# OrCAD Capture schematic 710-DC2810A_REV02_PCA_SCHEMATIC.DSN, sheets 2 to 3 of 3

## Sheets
2 LTM4673_PAGE2: size Custom
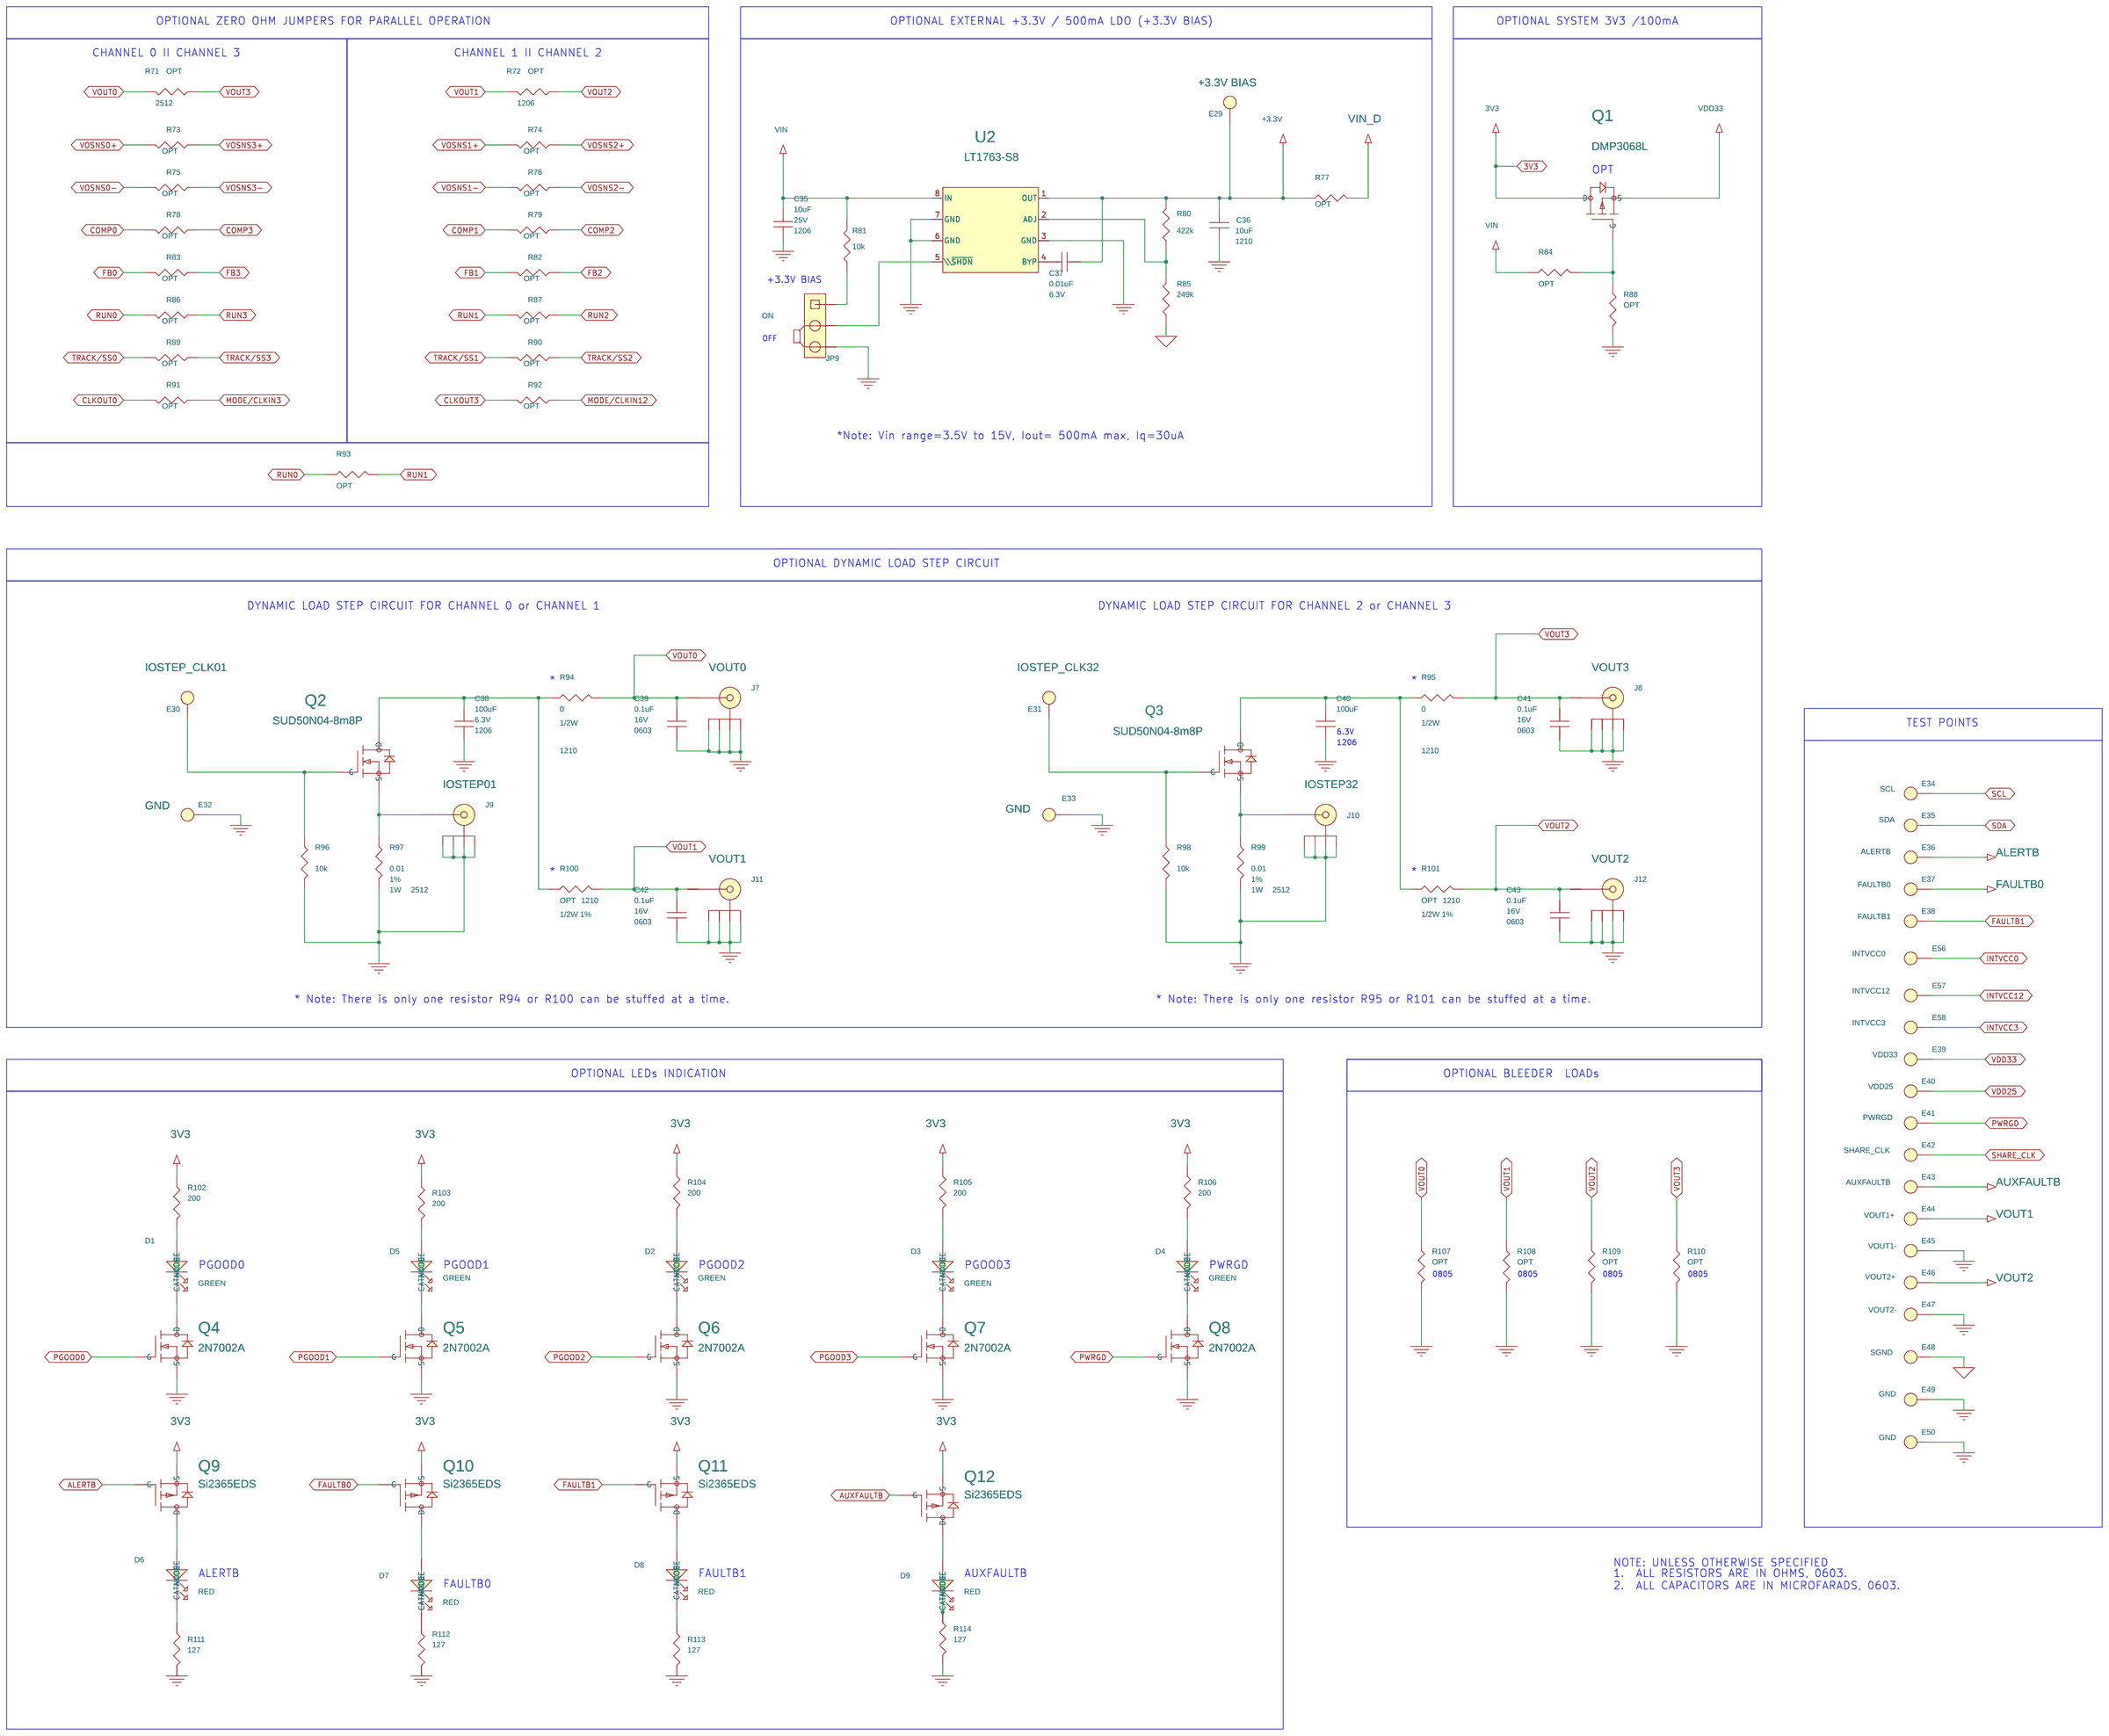
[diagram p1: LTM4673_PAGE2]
3 LTM4673_PAGE3: size Custom
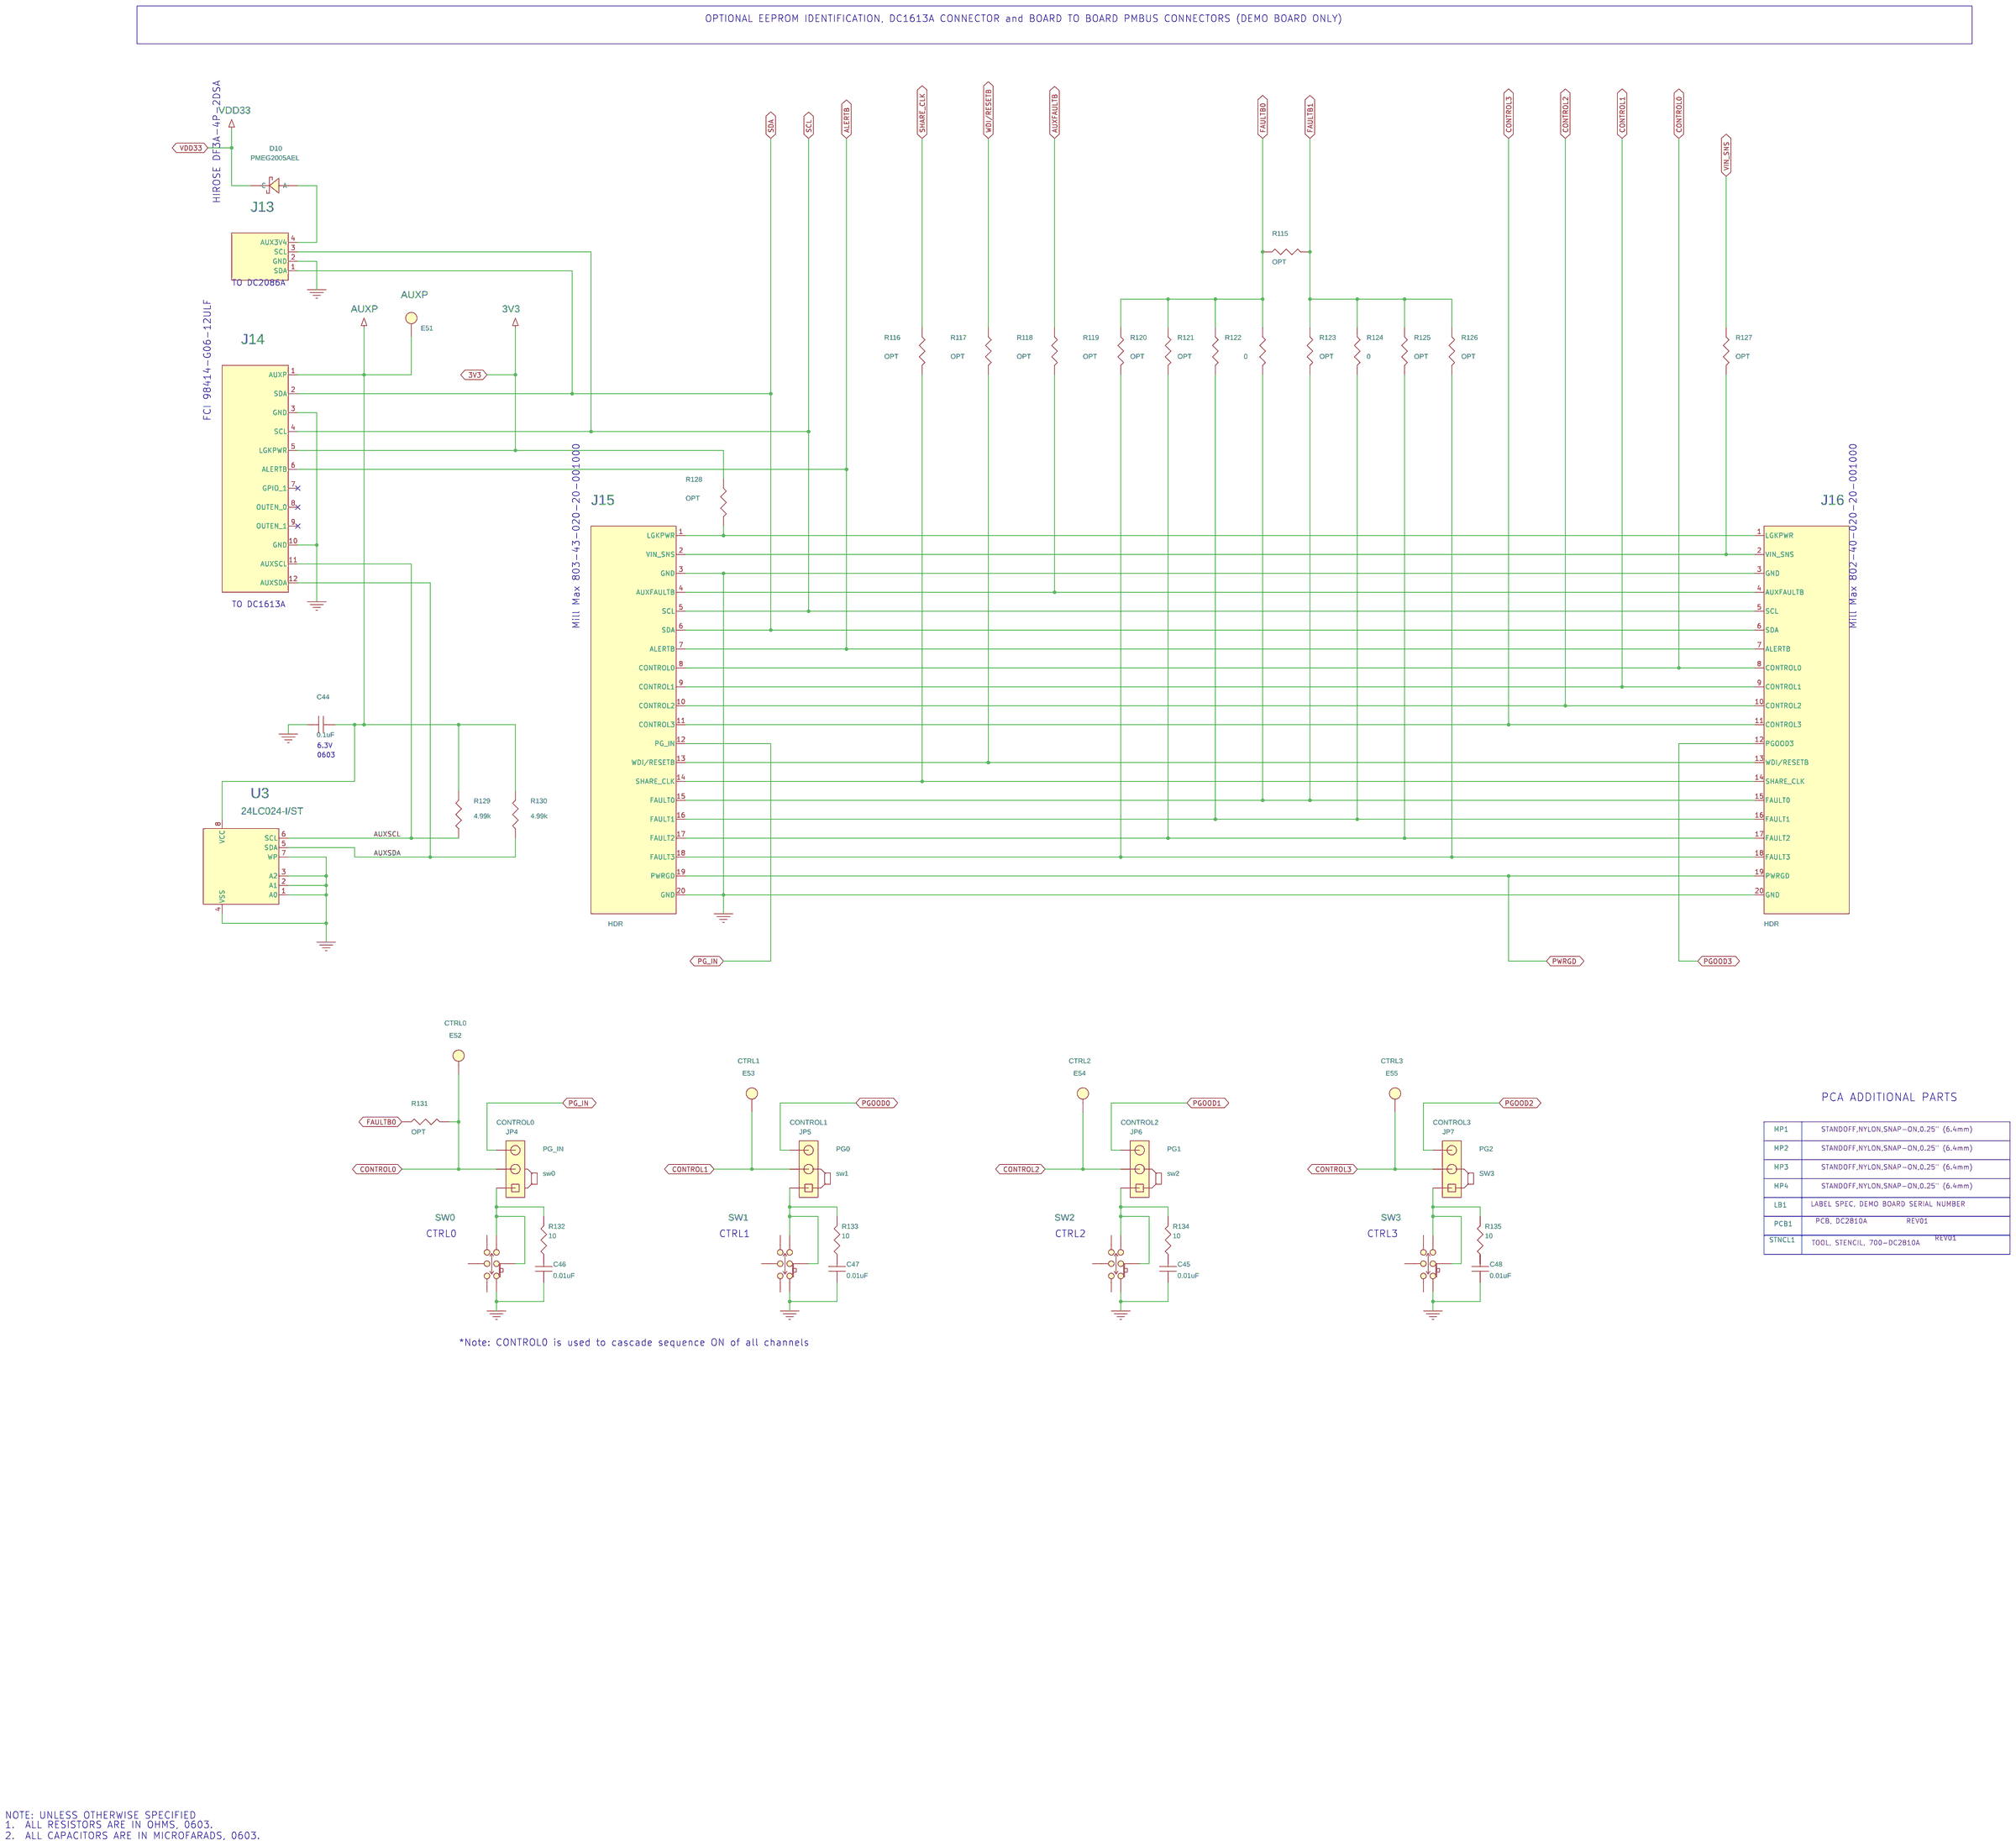
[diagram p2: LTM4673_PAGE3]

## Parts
sheet LTM4673_PAGE2
C35  10uF  [CC1206N]
C36  10uF  [CC1210N]
C37  0.01uF  [CC0603N]
C38  100uF  [CC1206N]
C39  0.1uF  [CC0603N]
C40  100uF  [CC1206N]
C41  0.1uF  [CC0603N]
C42  0.1uF  [CC0603N]
C43  0.1uF  [CC0603N]
D1  GREEN  [LED_0603]
D2  GREEN  [LED_0603]
D3  GREEN  [LED_0603]
D4  GREEN  [LED_0603]
D5  GREEN  [LED_0603]
D6  RED  [LED_0603]
D7  RED  [LED_0603]
D8  RED  [LED_0603]
D9  RED  [LED_0603]
E29  TEST POINT  [MILLMAX2308]
E30  TEST POINT  [MILLMAX2308]
E31  TEST POINT  [MILLMAX2308]
E32  TEST POINT  [MILLMAX2308]
E33  TEST POINT  [MILLMAX2308]
E34  TEST POINT  [MILLMAX2308]
E35  TEST POINT  [MILLMAX2308]
E36  TEST POINT  [MILLMAX2308]
E37  TEST POINT  [MILLMAX2308]
E38  TEST POINT  [MILLMAX2308]
E39  TEST POINT  [MILLMAX2308]
E40  TEST POINT  [MILLMAX2308]
E41  TEST POINT  [MILLMAX2308]
E42  TEST POINT  [MILLMAX2308]
E43  TEST POINT  [MILLMAX2308]
E44  TEST POINT  [MILLMAX2308]
E45  TEST POINT  [MILLMAX2308]
E46  TEST POINT  [MILLMAX2308]
E47  TEST POINT  [MILLMAX2308]
E48  TEST POINT  [MILLMAX2308]
E49  TEST POINT  [MILLMAX2308]
E50  TEST POINT  [MILLMAX2308]
E56  TEST POINT  [MILLMAX2308]
E57  TEST POINT  [MILLMAX2308]
E58  TEST POINT  [MILLMAX2308]
J7  RF,BNC  [CONNEX-112404]
J8  RF,BNC  [CONNEX-112404]
J9  RF,BNC  [CONNEX-112404]
J10  RF,BNC  [CONNEX-112404]
J11  RF,BNC  [CONNEX-112404]
J12  RF,BNC  [CONNEX-112404]
JP9  HDR.  [HD1X3-079]
Q1  DMP3068L  [SOT23-3N]
Q2  SUD50N04-8m8P  [TO-252-3N]
Q3  SUD50N04-8m8P  [TO-252-3N]
Q4  2N7002A  [SOT23-3N]
Q5  2N7002A  [SOT23-3N]
Q6  2N7002A  [SOT23-3N]
Q7  2N7002A  [SOT23-3N]
Q8  2N7002A  [SOT23-3N]
Q9  Si2365EDS  [SOT23-3N]
Q10  Si2365EDS  [SOT23-3N]
Q11  Si2365EDS  [SOT23-3N]
Q12  Si2365EDS  [SOT23-3N]
R71  OPT  [CR2512N]
R72  OPT  [CR1206N]
R73  OPT  [CR0603N]
R74  OPT  [CR0603N]
R75  OPT  [CR0603N]
R76  OPT  [CR0603N]
R77  OPT  [CR0603N]
R78  OPT  [CR0603N]
R79  OPT  [CR0603N]
R80  422k  [CR0603N]
R81  10k  [CR0603N]
R82  OPT  [CR0603N]
R83  OPT  [CR0603N]
R84  OPT  [CR0603N]
R85  249k  [CR0603N]
R86  OPT  [CR0603N]
R87  OPT  [CR0603N]
R88  OPT  [CR0603N]
R89  OPT  [CR0603N]
R90  OPT  [CR0603N]
R91  OPT  [CR0603N]
R92  OPT  [CR0603N]
R93  OPT  [CR0603N]
R94  0  [CR1210N]
R95  0  [CR1210N]
R96  10k  [CR0603N]
R97  0.01  [PANASONIC-ERJM1WS]
R98  10k  [CR0603N]
R99  0.01  [PANASONIC-ERJM1WS]
R100  OPT  [CR1210N]
R101  OPT  [CR1210N]
R102  200  [CR0603N]
R103  200  [CR0603N]
R104  200  [CR0603N]
R105  200  [CR0603N]
R106  200  [CR0603N]
R107  OPT  [CR0603N]
R108  OPT  [CR0603N]
R109  OPT  [CR0603N]
R110  OPT  [CR0603N]
R111  127  [CR0603N]
R112  127  [CR0603N]
R113  127  [CR0603N]
R114  127  [CR0603N]
U2  LT1763-S8  [LTC-S8-8-1610(S8)]
XJP9  SHUNT
sheet LTM4673_PAGE3
C44  0.1uF  [CC0603N]
C45  0.01uF  [CC0603N]
C46  0.01uF  [CC0603N]
C47  0.01uF  [CC0603N]
C48  0.01uF  [CC0603N]
D10  PMEG2005AEL  [SOD-882N]
E51  TEST POINT  [MILLMAX2308]
E52  TEST POINT  [MILLMAX2308]
E53  TEST POINT  [MILLMAX2308]
E54  TEST POINT  [MILLMAX2308]
E55  TEST POINT  [MILLMAX2308]
J13  SHROUDED HDR  [HIROSE-DF3A-4P-2DSA]
J14  SHROUDED HDR  [HD2X6-079-MOLEX]
J15  HDR  [MILL-MAX-803-43-020-20-001000]
J16  HDR  [MILL-MAX-802-40-020-20-001000]
JP4  HDR.  [HD1X3-079]
JP5  HDR.  [HD1X3-079]
JP6  HDR.  [HD1X3-079]
JP7  HDR.  [HD1X3-079]
LB1  LABEL  [895-0154_REV01]
MP1  STANDOFF  [MTG-8831]
MP2  STANDOFF  [MTG-8831]
MP3  STANDOFF  [MTG-8831]
MP4  STANDOFF  [MTG-8831]
PCB1  PCB, DC2810A
R115  OPT  [CR0603N]
R116  OPT  [CR0603N]
R117  OPT  [CR0603N]
R118  OPT  [CR0603N]
R119  OPT  [CR0603N]
R120  OPT  [CR0603N]
R121  OPT  [CR0603N]
R122  0  [CR0603N]
R123  OPT  [CR0603N]
R124  0  [CR0603N]
R125  OPT  [CR0603N]
R126  OPT  [CR0603N]
R127  OPT  [CR0603N]
R128  OPT  [CR0603N]
R129  4.99k  [CR0603N]
R130  4.99k  [CR0603N]
R131  OPT  [CR0603N]
R132  10  [CR0603N]
R133  10  [CR0603N]
R134  10  [CR0603N]
R135  10  [CR0603N]
STNCL1  TOOL, STENCIL, 700-DC2810A
SW0  DPDT  [CK-JS202011CQN]
SW1  DPDT  [CK-JS202011CQN]
SW2  DPDT  [CK-JS202011CQN]
SW3  DPDT  [CK-JS202011CQN]
U3  24LC024-I/ST  [MICROCHIP-TSSOP-8]
XJP4  SHUNT
XJP5  SHUNT
XJP6  SHUNT
XJP7  SHUNT

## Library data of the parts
C35 = CAP: CAP.,10uF,X7R,25V,10%,1206; CLASS: DISCRETE; Dielectric Type: X7R; FPLIST: CC1206N,CC1206L,CC1206M; Inventory Qty: 16158; Manufacturer: AVX; Manufacturer PN: 12063C106KAT2A; PART_NUMBER: 150-3318; Package Size: 1206; Rated Voltage: 25V; Tolerance: 10%
C36 = CAP: CAP.,10uF,X5R,16V,20%,1210; ALT_SYMBOLS: CC1210M, CC1210L; CLASS: DISCRETE; Dielectric Type: X5R; FPLIST: CC1210N,CC1210L,CC1210M; Inventory Qty: 6521; Manufacturer: AVX; Manufacturer PN: 1210YD106MAT2A; PART_NUMBER: 150-0099; Package Size: 1210; Rated Voltage: 16V; Tolerance: 20%
C37 = CAP: CAP.,0.01uF,X7R,6.3V,10%,0603; CLASS: DISCRETE; Dielectric Type: X7R; FPLIST: CC0603N,CC0603L,CC0603M; Inventory Qty: 11948; Manufacturer: AVX; Manufacturer PN: 06036C103KAT2A; PART_NUMBER: 150-3291; Package Size: 0603; Rated Voltage: 6.3V; Tolerance: 10%
C38 C40 = CAP: CAP.,100uF,X5R,6.3V,10%,1206; CLASS: DISCRETE; Dielectric Type: X5R; FPLIST: CC1206N,CC1206L,CC1206M; Inventory Qty: 6880; Manufacturer: MURATA; Manufacturer PN: GRM31CR60J107KE39L; PART_NUMBER: 150-2327; Package Size: 1206; Rated Voltage: 6.3V; Tolerance: 10%
C39 C41-C44 = CAP: CAP.,0.1uF,X7R,16V,10%,0603,FLEXITERM; CLASS: DISCRETE; Dielectric Type: X7R; FPLIST: CC0603N,CC0603L,CC0603M; Inventory Qty: 23721; Manufacturer: AVX; Manufacturer PN: 0603YC104KAZ2A; PART_NUMBER: 150-0165; Package Size: 0603; Rated Voltage: 16V; Tolerance: 10%
D1-D5 = LED: LED,GREEN,WATER CLEAR,0603; CLASS: DISCRETE; Inventory Qty: 6913; Manufacturer: WURTH ELEKTRONIK; Manufacturer PN: 150060GS75000; PART_NUMBER: 270-0057; Package Type: 0603
D6-D9 = LED: LED,RED,WATER CLEAR,0603; CLASS: DISCRETE; Inventory Qty: 928; Label: GREEN; Manufacturer: WURTH ELEKTRONIK; Manufacturer PN: 150060RS75000; PART_NUMBER: 270-0071; Package Type: 0603
E29 = TEST_POINT_.156_MILL-MAX_2308: TEST POINT,TURRET,0.064" MTG. HOLE,PCB 0.062" THK; CLASS: IO; Inventory Qty: 767848; Manufacturer: MILL-MAX; Manufacturer PN: 2308-2-00-80-00-00-07-0; PART_FIELD_01: +3.3V BIAS; PART_NUMBER: 260-0004
E30 = TEST_POINT_.156_MILL-MAX_2308: TEST POINT,TURRET,0.064" MTG. HOLE,PCB 0.062" THK; CLASS: IO; Inventory Qty: 767848; Manufacturer: MILL-MAX; Manufacturer PN: 2308-2-00-80-00-00-07-0; PART_FIELD_01: IOSTEP_CLK01; PART_NUMBER: 260-0004
E31 = TEST_POINT_.156_MILL-MAX_2308: TEST POINT,TURRET,0.064" MTG. HOLE,PCB 0.062" THK; CLASS: IO; Inventory Qty: 767848; Manufacturer: MILL-MAX; Manufacturer PN: 2308-2-00-80-00-00-07-0; PART_FIELD_01: IOSTEP_CLK32; PART_NUMBER: 260-0004
E32 E33 E49 E50 = TEST_POINT_.156_MILL-MAX_2308: TEST POINT,TURRET,0.064" MTG. HOLE,PCB 0.062" THK; CLASS: IO; Inventory Qty: 767848; Manufacturer: MILL-MAX; Manufacturer PN: 2308-2-00-80-00-00-07-0; PART_FIELD_01: GND; PART_NUMBER: 260-0004
E34 = TEST_POINT_.156_MILL-MAX_2308: TEST POINT,TURRET,0.064" MTG. HOLE,PCB 0.062" THK; CLASS: IO; Inventory Qty: 767848; Manufacturer: MILL-MAX; Manufacturer PN: 2308-2-00-80-00-00-07-0; PART_FIELD_01: SCL; PART_NUMBER: 260-0004
E35 = TEST_POINT_.156_MILL-MAX_2308: TEST POINT,TURRET,0.064" MTG. HOLE,PCB 0.062" THK; CLASS: IO; Inventory Qty: 767848; Manufacturer: MILL-MAX; Manufacturer PN: 2308-2-00-80-00-00-07-0; PART_FIELD_01: SDA; PART_NUMBER: 260-0004
E36 = TEST_POINT_.156_MILL-MAX_2308: TEST POINT,TURRET,0.064" MTG. HOLE,PCB 0.062" THK; CLASS: IO; Inventory Qty: 767848; Manufacturer: MILL-MAX; Manufacturer PN: 2308-2-00-80-00-00-07-0; PART_FIELD_01: ALERTB; PART_NUMBER: 260-0004
E37 = TEST_POINT_.156_MILL-MAX_2308: TEST POINT,TURRET,0.064" MTG. HOLE,PCB 0.062" THK; CLASS: IO; Inventory Qty: 767848; Manufacturer: MILL-MAX; Manufacturer PN: 2308-2-00-80-00-00-07-0; PART_FIELD_01: FAULTB0; PART_NUMBER: 260-0004
E38 = TEST_POINT_.156_MILL-MAX_2308: TEST POINT,TURRET,0.064" MTG. HOLE,PCB 0.062" THK; CLASS: IO; Inventory Qty: 767848; Manufacturer: MILL-MAX; Manufacturer PN: 2308-2-00-80-00-00-07-0; PART_FIELD_01: FAULTB1; PART_NUMBER: 260-0004
E39 = TEST_POINT_.156_MILL-MAX_2308: TEST POINT,TURRET,0.064" MTG. HOLE,PCB 0.062" THK; CLASS: IO; Inventory Qty: 767848; Manufacturer: MILL-MAX; Manufacturer PN: 2308-2-00-80-00-00-07-0; PART_FIELD_01: VDD33; PART_NUMBER: 260-0004
E40 = TEST_POINT_.156_MILL-MAX_2308: TEST POINT,TURRET,0.064" MTG. HOLE,PCB 0.062" THK; CLASS: IO; Inventory Qty: 767848; Manufacturer: MILL-MAX; Manufacturer PN: 2308-2-00-80-00-00-07-0; PART_FIELD_01: VDD25; PART_NUMBER: 260-0004
E41 = TEST_POINT_.156_MILL-MAX_2308: TEST POINT,TURRET,0.064" MTG. HOLE,PCB 0.062" THK; CLASS: IO; Inventory Qty: 767848; Manufacturer: MILL-MAX; Manufacturer PN: 2308-2-00-80-00-00-07-0; PART_FIELD_01: PWRGD; PART_NUMBER: 260-0004
E42 = TEST_POINT_.156_MILL-MAX_2308: TEST POINT,TURRET,0.064" MTG. HOLE,PCB 0.062" THK; CLASS: IO; Inventory Qty: 767848; Manufacturer: MILL-MAX; Manufacturer PN: 2308-2-00-80-00-00-07-0; PART_FIELD_01: SHARE_CLK; PART_NUMBER: 260-0004
E43 = TEST_POINT_.156_MILL-MAX_2308: TEST POINT,TURRET,0.064" MTG. HOLE,PCB 0.062" THK; CLASS: IO; Inventory Qty: 767848; Manufacturer: MILL-MAX; Manufacturer PN: 2308-2-00-80-00-00-07-0; PART_FIELD_01: AUXFAULTB; PART_NUMBER: 260-0004
E44 = TEST_POINT_.156_MILL-MAX_2308: TEST POINT,TURRET,0.064" MTG. HOLE,PCB 0.062" THK; CLASS: IO; Inventory Qty: 767848; Manufacturer: MILL-MAX; Manufacturer PN: 2308-2-00-80-00-00-07-0; PART_FIELD_01: VOUT1+; PART_NUMBER: 260-0004
E45 = TEST_POINT_.156_MILL-MAX_2308: TEST POINT,TURRET,0.064" MTG. HOLE,PCB 0.062" THK; CLASS: IO; Inventory Qty: 767848; Manufacturer: MILL-MAX; Manufacturer PN: 2308-2-00-80-00-00-07-0; PART_FIELD_01: VOUT1-; PART_NUMBER: 260-0004
E46 = TEST_POINT_.156_MILL-MAX_2308: TEST POINT,TURRET,0.064" MTG. HOLE,PCB 0.062" THK; CLASS: IO; Inventory Qty: 767848; Manufacturer: MILL-MAX; Manufacturer PN: 2308-2-00-80-00-00-07-0; PART_FIELD_01: VOUT2+; PART_NUMBER: 260-0004
E47 = TEST_POINT_.156_MILL-MAX_2308: TEST POINT,TURRET,0.064" MTG. HOLE,PCB 0.062" THK; CLASS: IO; Inventory Qty: 767848; Manufacturer: MILL-MAX; Manufacturer PN: 2308-2-00-80-00-00-07-0; PART_FIELD_01: VOUT2-; PART_NUMBER: 260-0004
E48 = TEST_POINT_.156_MILL-MAX_2308: TEST POINT,TURRET,0.064" MTG. HOLE,PCB 0.062" THK; CLASS: IO; Inventory Qty: 767848; Manufacturer: MILL-MAX; Manufacturer PN: 2308-2-00-80-00-00-07-0; PART_FIELD_01: SGND; PART_NUMBER: 260-0004
E56 = TEST_POINT_.156_MILL-MAX_2308: TEST POINT,TURRET,0.064" MTG. HOLE,PCB 0.062" THK; CLASS: IO; Inventory Qty: 767848; Manufacturer: MILL-MAX; Manufacturer PN: 2308-2-00-80-00-00-07-0; PART_FIELD_01: INTVCC0; PART_NUMBER: 260-0004
E57 = TEST_POINT_.156_MILL-MAX_2308: TEST POINT,TURRET,0.064" MTG. HOLE,PCB 0.062" THK; CLASS: IO; Inventory Qty: 767848; Manufacturer: MILL-MAX; Manufacturer PN: 2308-2-00-80-00-00-07-0; PART_FIELD_01: INTVCC12; PART_NUMBER: 260-0004
E58 = TEST_POINT_.156_MILL-MAX_2308: TEST POINT,TURRET,0.064" MTG. HOLE,PCB 0.062" THK; CLASS: IO; Inventory Qty: 767848; Manufacturer: MILL-MAX; Manufacturer PN: 2308-2-00-80-00-00-07-0; PART_FIELD_01: INTVCC3; PART_NUMBER: 260-0004
J7 = BNC_50_OHM_112404_C: CONN.,RF,BNC,RCPT JACK,5-PIN,STR,THT,50 OHMS; CLASS: IO; Inventory Qty: 83605; Manufacturer: AMPHENOL RF; Manufacturer PN: 112404; PART_FIELD_01: VOUT0; PART_NUMBER: 250-0427
J8 = BNC_50_OHM_112404_C: CONN.,RF,BNC,RCPT JACK,5-PIN,STR,THT,50 OHMS; CLASS: IO; Inventory Qty: 83605; Manufacturer: AMPHENOL RF; Manufacturer PN: 112404; PART_FIELD_01: VOUT3; PART_NUMBER: 250-0427
J9 = BNC_50_OHM_112404_C: CONN.,RF,BNC,RCPT JACK,5-PIN,STR,THT,50 OHMS; CLASS: IO; Inventory Qty: 83605; Manufacturer: AMPHENOL RF; Manufacturer PN: 112404; PART_FIELD_01: IOSTEP01; PART_NUMBER: 250-0427
J10 = BNC_50_OHM_112404_C: CONN.,RF,BNC,RCPT JACK,5-PIN,STR,THT,50 OHMS; CLASS: IO; Inventory Qty: 83605; Manufacturer: AMPHENOL RF; Manufacturer PN: 112404; PART_FIELD_01: IOSTEP32; PART_NUMBER: 250-0427
J11 = BNC_50_OHM_112404_C: CONN.,RF,BNC,RCPT JACK,5-PIN,STR,THT,50 OHMS; CLASS: IO; Inventory Qty: 83605; Manufacturer: AMPHENOL RF; Manufacturer PN: 112404; PART_FIELD_01: VOUT1; PART_NUMBER: 250-0427
J12 = BNC_50_OHM_112404_C: CONN.,RF,BNC,RCPT JACK,5-PIN,STR,THT,50 OHMS; CLASS: IO; Inventory Qty: 83605; Manufacturer: AMPHENOL RF; Manufacturer PN: 112404; PART_FIELD_01: VOUT2; PART_NUMBER: 250-0427
JP9 = 1X3_B: CONN.,HDR.,MALE,1x3,2mm,THT, STR,NO SUBS. ALLOWED; 11th Part Field: ON; CLASS: IO; FPLIST: HD1X3-079,JP3X1/079; Inventory Qty: 9292; Manufacturer: SAMTEC; Manufacturer PN: TMM-103-02-L-S; PART_NUMBER: 250-0638
Q1 = 3P_P-CH_TYPE1A: XSTR.,MOSFET, P-CH,30V,3.3A,SOT23-3; CLASS: DISCRETE; Inventory Qty: 2390; Manufacturer: DIODES INC.; Manufacturer PN: DMP3068L-7; PART_NUMBER: 240-0321; Package Type: SOT23-3; Rated Voltage: 30V
Q2 Q3 = 3P_N-CH_TYPE2A: XSTR.,MOSFET,N-CH,40V,14A,TO-252 (DPAK); CLASS: DISCRETE; Inventory Qty: 26948; Manufacturer: VISHAY; Manufacturer PN: SUD50N04-8M8P-4GE3; PART_NUMBER: 240-0021; Package Type: TO-252 (DPAK); Rated Voltage: 40V
Q4-Q8 = 3P_N-CH_TYPE1A: XSTR.,MOSFET,N-CH,60V,220mA,SOT23-3,AEC-Q101; CLASS: DISCRETE; Inventory Qty: 8162; Manufacturer: DIODES INC.; Manufacturer PN: 2N7002A-13; PART_NUMBER: 240-0059; Package Type: SOT23-3; Rated Voltage: 60V
Q9-Q12 = 3P_P-CH_TYPE1A: XSTR.,MOSFET, P-CH,20V,5.9A,TO-236 (SOT23-3); CLASS: DISCRETE; Inventory Qty: 16867; Manufacturer: VISHAY; Manufacturer PN: Si2365EDS-T1-GE3; PART_NUMBER: 240-0119; Package Size: SOT-23; Package Type: TO-236 (SOT23-3); Rated Voltage: 20V
R71 = RES: RES., OPTION, 2512; CLASS: DISCRETE; FPLIST: CR2512N,CR2512L,CR2512M; PART_NUMBER: 100-2376; Package Size: 2512
R72 = RES: RES., OPTION, 1206; CLASS: DISCRETE; FPLIST: CR1206N,CR1206L,CR1206M; PART_NUMBER: 100-2459; Package Size: 1206
R73-R79 R82-R84 R86-R93 R107-R110 R115-R121 R123 R125-R128 R131 = RES: RES., OPTION, 0603; CLASS: DISCRETE; FPLIST: CR0603N,CR0603L,CR0603M; PART_NUMBER: 100-2374; Package Size: 0603
R80 = RES: RES.,422k OHMS,1%,1/10W,0603,AEC-Q200; CLASS: DISCRETE; FPLIST: CR0603N,CR0603L,CR0603M; Inventory Qty: 9632; Manufacturer: NIC; Manufacturer PN: NRC06F4223TRF; PART_NUMBER: 100-2594; Package Size: 0603; Rated Power: 1/10W; Temperature Coefficient: 100ppm/C; Tolerance: 1%
R81 R96 R98 = RES: RES.,10k OHMS,1%,1/10W,0603; CLASS: DISCRETE; FPLIST: CR0603N,CR0603L,CR0603M; Inventory Qty: 74893; Manufacturer: VISHAY; Manufacturer PN: CRCW060310K0FKEC; PART_NUMBER: 100-2532; Package Size: 0603; Rated Power: 1/10W; Temperature Coefficient: 100ppm/C; Tolerance: 1%
R85 = RES: RES.,249k OHMS,1%,1/10W,0603; CLASS: DISCRETE; FPLIST: CR0603N,CR0603L,CR0603M; Inventory Qty: 9984; Manufacturer: YAGEO; Manufacturer PN: RC0603FR-07249KL; PART_NUMBER: 100-2616; Package Size: 0603; Rated Power: 1/10W; Temperature Coefficient: 100ppm/C; Tolerance: 1%
R94 R95 = RES: RES.,0 OHM,1/2W,1210,AEC-Q200; CLASS: DISCRETE; FPLIST: CR1210N,CR1210L,CR1210M; Inventory Qty: 26438; Manufacturer: VISHAY; Manufacturer PN: CRCW12100000Z0EA; PART_NUMBER: 100-2973; Package Size: 1210; Rated Power: 1/2W
R97 R99 = RES: RES.,0.01 OHM,1%,1W,2512,METAL,SENSE; CLASS: DISCRETE; FPLIST: CR2512N,CR2512L,CR2512M; Inventory Qty: 13175; Manufacturer: PANASONIC; Manufacturer PN: ERJM1WSF10MU; PART_NUMBER: 100-0248; Package Size: 2512; Rated Power: 1W; Temperature Coefficient: 100ppm/C; Tolerance: 1%
R100 R101 = RES: RES., OPTION, 1210; BOM Notes: R100,R101= 1/2W 1%; CLASS: DISCRETE; FPLIST: CR1210N,CR1210L,CR1210M; PART_FIELD_01: 1/2W 1%; PART_NUMBER: 100-0100; Package Size: 1210
R102-R106 = RES: RES.,200 OHMS,1%,1/10W,0603; CLASS: DISCRETE; FPLIST: CR0603N,CR0603L,CR0603M; Inventory Qty: 42882; Label: OPT 0; Manufacturer: VISHAY; Manufacturer PN: CRCW0603200RFKEA; PART_NUMBER: 100-0130; Package Size: 0603; Rated Power: 1/10W; Temperature Coefficient: 100ppm; Tolerance: 1%
R111-R114 = RES: RES.,127 OHMS,1%,1/10W,0603,AEC-Q200; CLASS: DISCRETE; FPLIST: CR0603N,CR0603L,CR0603M; Inventory Qty: 81757; Label: OPT 0; Manufacturer: NIC; Manufacturer PN: NRC06F1270TRF; PART_NUMBER: 100-0054; Package Size: 0603; Rated Power: 1/10W; Temperature Coefficient: 100ppm/C; Tolerance: 1%
U2 = LT1763-S8: IC,500mA, LDO uPOWER REGULATOR,SO-8,ADJ.; CLASS: IC; Inventory Qty: 0; Manufacturer: LINEAR TECH.; Manufacturer PN: LT1763CS8#PBF; PART_NUMBER: LT1763CS8#PBF; Package Size: LTC-S8; Package Type: SO-8
XJP4-XJP7 XJP9 = SHUNT_2MM: CONN.,SHUNT,FEMALE,2-POS,2mm; CLASS: IO; Inventory Qty: 97153; Manufacturer: SAMTEC; Manufacturer PN: 2SN-BK-G; PART_NUMBER: 250-0419
C45-C48 = CAP: CAP.,0.01uF,X7R,16V,10%,0603; CLASS: DISCRETE; Dielectric Type: X7R; FPLIST: CC0603N,CC0603L,CC0603M; Inventory Qty: 69461; Manufacturer: AVX; Manufacturer PN: 0603YC103KAT2A; PART_NUMBER: 150-0038; Package Size: 0603; Rated Voltage: 16V; Tolerance: 10%
D10 = DIODE_SCHOTTKY_A: DIODE,SCHOTTKY,20V,0.5A,SOD-882,LEADLESS; CLASS: DISCRETE; Inventory Qty: 13557; Manufacturer: NEXPERIA; Manufacturer PN: PMEG2005AEL,315; Max Forward Current or Rated Power: 0.5A; PART_NUMBER: 210-0105; Package Type: SOD-882; Rated Voltage: 20V; Rated Voltage or Zener Voltage: 20V
E51 = TEST_POINT_.156_MILL-MAX_2308: TEST POINT,TURRET,0.064" MTG. HOLE,PCB 0.062" THK; CLASS: IO; Inventory Qty: 767848; Manufacturer: MILL-MAX; Manufacturer PN: 2308-2-00-80-00-00-07-0; PART_FIELD_01: AUXP; PART_NUMBER: 260-0004
E52 = TEST_POINT_.156_MILL-MAX_2308: TEST POINT,TURRET,0.064" MTG. HOLE,PCB 0.062" THK; CLASS: IO; Inventory Qty: 767848; Manufacturer: MILL-MAX; Manufacturer PN: 2308-2-00-80-00-00-07-0; PART_FIELD_01: CTRL0; PART_NUMBER: 260-0004
E53 = TEST_POINT_.156_MILL-MAX_2308: TEST POINT,TURRET,0.064" MTG. HOLE,PCB 0.062" THK; CLASS: IO; Inventory Qty: 767848; Manufacturer: MILL-MAX; Manufacturer PN: 2308-2-00-80-00-00-07-0; PART_FIELD_01: CTRL1; PART_NUMBER: 260-0004
E54 = TEST_POINT_.156_MILL-MAX_2308: TEST POINT,TURRET,0.064" MTG. HOLE,PCB 0.062" THK; CLASS: IO; Inventory Qty: 767848; Manufacturer: MILL-MAX; Manufacturer PN: 2308-2-00-80-00-00-07-0; PART_FIELD_01: CTRL2; PART_NUMBER: 260-0004
E55 = TEST_POINT_.156_MILL-MAX_2308: TEST POINT,TURRET,0.064" MTG. HOLE,PCB 0.062" THK; CLASS: IO; Inventory Qty: 767848; Manufacturer: MILL-MAX; Manufacturer PN: 2308-2-00-80-00-00-07-0; PART_FIELD_01: CTRL3; PART_NUMBER: 260-0004
J13 = CONN_DC2086: CONN.,SHROUDED HDR,MALE,1x4,2mm,VERT,STR,THT; CLASS: IO; Inventory Qty: 5900; Manufacturer: HIROSE ELECTRIC; Manufacturer PN: DF3A-4P-2DSA; PART_NUMBER: 250-0491
J14 = CONN_7._FCI_12_POS_2MM: CONN.,SHROUDED HDR,MALE,2x6,2mm,VERT,STR,THT; CLASS: IO; Inventory Qty: 13967; Manufacturer: FCI; Manufacturer PN: 98414-G06-12ULF; PART_NUMBER: 250-0433
J15 = PMBUS_20PIN_FEMALE: CONN.,HDR,RCPT,2x10,2.54mm,R/A THT; CLASS: IO; Inventory Qty: 2664; Manufacturer: Mill-Max; Manufacturer PN: 803-43-020-20-001000; PART_NUMBER: 250-0432
J16 = PMBUS_20PIN_MALE: CONN.,HDR,MALE,2x10,2.54mm,R/A THT; CLASS: IO; Inventory Qty: 311; Manufacturer: Mill-Max; Manufacturer PN: 802-40-020-20-001000; PART_NUMBER: 250-0434
JP4 = 1X3_B: CONN.,HDR.,MALE,1x3,2mm,THT, STR,NO SUBS. ALLOWED; 11th Part Field: PG_IN; 12th Part Field: CONTROL0; 9th Part Field: sw0; CLASS: IO; FPLIST: HD1X3-079,JP3X1/079; Inventory Qty: 9292; Manufacturer: SAMTEC; Manufacturer PN: TMM-103-02-L-S; PART_NUMBER: 250-0638
JP5 = 1X3_B: CONN.,HDR.,MALE,1x3,2mm,THT, STR,NO SUBS. ALLOWED; 11th Part Field: PG0; 12th Part Field: CONTROL1; 9th Part Field: sw1; CLASS: IO; FPLIST: HD1X3-079,JP3X1/079; Inventory Qty: 9292; Manufacturer: SAMTEC; Manufacturer PN: TMM-103-02-L-S; PART_NUMBER: 250-0638
JP6 = 1X3_B: CONN.,HDR.,MALE,1x3,2mm,THT, STR,NO SUBS. ALLOWED; 11th Part Field: PG1; 12th Part Field: CONTROL2; 9th Part Field: sw2; CLASS: IO; FPLIST: HD1X3-079,JP3X1/079; Inventory Qty: 9292; Manufacturer: SAMTEC; Manufacturer PN: TMM-103-02-L-S; PART_NUMBER: 250-0638
JP7 = 1X3_B: CONN.,HDR.,MALE,1x3,2mm,THT, STR,NO SUBS. ALLOWED; 11th Part Field: PG2; 12th Part Field: CONTROL3; 9th Part Field: SW3; CLASS: IO; FPLIST: HD1X3-079,JP3X1/079; Inventory Qty: 9292; Manufacturer: SAMTEC; Manufacturer PN: TMM-103-02-L-S; PART_NUMBER: 250-0638
LB1 = BLANK_LABEL: LABEL SPEC, DEMO BOARD SERIAL NUMBER; Inventory Qty: 0; Manufacturer: BRADY; Manufacturer PN: THT-96-717-10; PART_NUMBER: 895-0154
MP1-MP4 = BLANK_MECHANICAL_PART: STANDOFF,NYLON,SNAP-ON,0.25" (6.4mm); CLASS: MECHANICAL PART; Inventory Qty: 191576; Manufacturer: KEYSTONE; Manufacturer PN: 8831; PART_NUMBER: 763-0006
PCB1 = BLANK_PCB_PART: BOM Notes: REV01; CLASS: DISCRETE; Inventory Qty: 0; Manufacturer: MAO BANG; Manufacturer PN: 600-DC2810A; PART_NUMBER: 600-DC2810A
R122 R124 = RES: RES.,0 OHM,1/10W,0603,AEC-Q200; CLASS: DISCRETE; FPLIST: CR0603N,CR0603L,CR0603M; Inventory Qty: 601530; Manufacturer: VISHAY; Manufacturer PN: CRCW06030000Z0EA; PART_NUMBER: 100-0009; Package Size: 0603; Rated Power: 1/10W
R129 R130 = RES: RES.,4.99k OHMS,1%,1/10W,0603; CLASS: DISCRETE; FPLIST: CR0603N,CR0603L,CR0603M; Inventory Qty: 73627; Manufacturer: PANASONIC; Manufacturer PN: ERJ3EKF4991V; PART_NUMBER: 100-0121; Package Size: 0603; Rated Power: 1/10W; Temperature Coefficient: 100ppm/C; Tolerance: 1%
R132-R135 = RES: RES.,10 OHMS,1%,1/10W,0603; CLASS: DISCRETE; FPLIST: CR0603N,CR0603L,CR0603M; Inventory Qty: 149976; Manufacturer: VISHAY; Manufacturer PN: CRCW060310R0FKEA; PART_NUMBER: 100-2306; Package Size: 0603; Part Number: VISHAY CRCW060310K0JNEA; Rated Power: 1/10W; Temperature Coefficient: 100ppm/C; Tolerance: 1%
STNCL1 = BLANK_STENCIL_PART: BOM Notes: REV01; CLASS: DISCRETE; Inventory Qty: 0; Manufacturer: LINEAR TECH.; Manufacturer PN: 830-DC2810A; PART_NUMBER: 830-DC2810A
SW0-SW3 = SW-DPDT-JS202011CQN_ALT1: SWITCH,SLIDE,DPDT,0.3A,6VDC,PTH; CLASS: DISCRETE; Inventory Qty: 24297; Manufacturer: C&K; Manufacturer PN: JS202011CQN; PART_NUMBER: 430-0039
U3 = 24LC024-I_ST_TSSOP-8: IC,EEPROM, I2C,TSSOP-8,2Kb (256 x 8), 400kHz; CLASS: IC; Inventory Qty: 6716; Manufacturer: MICROCHIP; PART_NUMBER: 280-0494; Package Size: TSSOP-8; Package Type: TSSOP-8

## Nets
3V3: J14.5(LGKPWR) Q1.3(D) Q9.2(S) Q10.2(S) Q11.2(S) Q12.2(S) R102.1 R103.1 R104.1 R105.1 R106.1 R128.1
+3.3V: C36.2 C37.2 E29.1(A) R77.1 R80.2 U2.1(OUT)
GND_POWER: C35.2 C36.1 C38.2 C39.2 C40.2 C41.2 C42.2 C43.2 C44.1 C45.1 C46.1 C47.1 C48.1 E32.1(A) E33.1(A) E45.1(A) E47.1(A) E49.1(A) E50.1(A) J7.2 J7.3 J7.4 J7.5 J8.2 J8.3 J8.4 J8.5 J9.2 J9.3 J9.4 J9.5 J10.2 J10.3 J10.4 J10.5 J11.2 J11.3 J11.4 J11.5 J12.2 J12.3 J12.4 J12.5 J13.2(GND) J14.3(GND) J14.10(GND) J15.3(GND) J15.20(GND) J16.3(GND) J16.20(GND) JP9.3 Q4.2(S) Q5.2(S) Q6.2(S) Q7.2(S) Q8.2(S) R88.2 R96.2 R97.2 R98.2 R99.2 R107.2 R108.2 R109.2 R110.2 R111.2 R112.2 R113.2 R114.2 SW0.3 SW1.3 SW2.3 SW3.3 U2.3(GND) U2.6(GND) U2.7(GND) U3.1(A0) U3.2(A1) U3.3(A2) U3.4(VSS) U3.7(WP) ; also on sheet 1
GND_SIGNAL: E48.1(A) R85.1 ; also on sheet 1
VDD25: E40.1(A) ; also on sheet 1
VDD33: D10.1(C) E39.1(A) Q1.2(S) ; also on sheet 1
VIN: C35.1 R81.2 R84.1 U2.8(IN) ; also on sheet 1
VIN_D: R77.2 ; also on sheet 1
VIN_SNS: R127.1 ; also on sheet 1
ALERTB: E36.1(A) J14.6(ALERTB) J15.7(ALERTB) J16.7(ALERTB) Q9.1(G) ; also on sheet 1
AUXFAULTB: E43.1(A) Q12.1(G) R118.1 ; also on sheet 1
AUXP: C44.2 E51.1(A) J14.1(AUXP) R129.2 R130.2 U3.8(VCC)
AUXSCL: J14.11(AUXSCL) R129.1 U3.6(SCL)
AUXSDA: J14.12(AUXSDA) R130.1 U3.5(SDA)
CLKOUT0: R91.1 ; also on sheet 1
CLKOUT3: R92.1 ; also on sheet 1
COMP0: R78.1 ; also on sheet 1
COMP1: R79.1 ; also on sheet 1
COMP2: R79.2 ; also on sheet 1
COMP3: R78.2 ; also on sheet 1
CONTROL0: E52.1(A) J15.8(CONTROL0) J16.8(CONTROL0) JP4.2 R131.2 ; also on sheet 1
CONTROL1: E53.1(A) J15.9(CONTROL1) J16.9(CONTROL1) JP5.2 ; also on sheet 1
CONTROL2: E54.1(A) J15.10(CONTROL2) J16.10(CONTROL2) JP6.2 ; also on sheet 1
CONTROL3: E55.1(A) J15.11(CONTROL3) J16.11(CONTROL3) JP7.2 ; also on sheet 1
FAULTB0: E37.1(A) Q10.1(G) R115.1 R119.1 R120.1 R121.1 R122.1 R131.1 ; also on sheet 1
FAULTB1: E38.1(A) Q11.1(G) R115.2 R123.1 R124.1 R125.1 R126.1 ; also on sheet 1
FB0: R83.1 ; also on sheet 1
FB1: R82.1 ; also on sheet 1
FB2: R82.2 ; also on sheet 1
FB3: R83.2 ; also on sheet 1
INTVCC0: E56.1(A) ; also on sheet 1
INTVCC3: E58.1(A) ; also on sheet 1
INTVCC12: E57.1(A) ; also on sheet 1
MODE/CLKIN3: R91.2 ; also on sheet 1
MODE/CLKIN12: R92.2 ; also on sheet 1
PG_IN: J15.12(PG_IN) JP4.3
PGOOD0: JP5.3 Q4.1(G) ; also on sheet 1
PGOOD1: JP6.3 Q5.1(G) ; also on sheet 1
PGOOD2: JP7.3 Q6.1(G) ; also on sheet 1
PGOOD3: J16.12(PGOOD3) Q7.1(G) ; also on sheet 1
PWRGD: E41.1(A) J15.19(PWRGD) J16.19(PWRGD) Q8.1(G) ; also on sheet 1
RUN0: R86.1 R93.1 ; also on sheet 1
RUN1: R87.1 R93.2 ; also on sheet 1
RUN2: R87.2 ; also on sheet 1
RUN3: R86.2 ; also on sheet 1
SCL: E34.1(A) J13.3(SCL) J14.4(SCL) J15.5(SCL) J16.5(SCL) ; also on sheet 1
SDA: E35.1(A) J13.1(SDA) J14.2(SDA) J15.6(SDA) J16.6(SDA) ; also on sheet 1
SHARE_CLK: E42.1(A) R116.1 ; also on sheet 1
TRACK/SS0: R89.1 ; also on sheet 1
TRACK/SS1: R90.1 ; also on sheet 1
TRACK/SS2: R90.2 ; also on sheet 1
TRACK/SS3: R89.2 ; also on sheet 1
VOSNS0+: R73.1 ; also on sheet 1
VOSNS0-: R75.1 ; also on sheet 1
VOSNS1+: R74.1 ; also on sheet 1
VOSNS1-: R76.1 ; also on sheet 1
VOSNS2+: R74.2 ; also on sheet 1
VOSNS2-: R76.2 ; also on sheet 1
VOSNS3+: R73.2 ; also on sheet 1
VOSNS3-: R75.2 ; also on sheet 1
VOUT0: C39.1 J7.1 R71.1 R94.2 R107.1 ; also on sheet 1
VOUT1: C42.1 E44.1(A) J11.1 R72.1 R100.2 R108.1 ; also on sheet 1
VOUT2: C43.1 E46.1(A) J12.1 R72.2 R101.2 R109.1 ; also on sheet 1
VOUT3: C41.1 J8.1 R71.2 R95.2 R110.1 ; also on sheet 1
WDI/RESETB: R117.1 ; also on sheet 1
N20336682: JP9.1 R81.1
N20355400: C38.1 Q2.2(D) R94.1 R100.1
N20355495: E30.1(A) Q2.1(G) R96.1
N20359285: J9.1 Q2.3(S) R97.1
N20368102: C40.1 Q3.2(D) R95.1 R101.1
N20368141: E31.1(A) Q3.1(G) R98.1
N20368268: J10.1 Q3.3(S) R99.1
N20417877: D10.2(A) J13.4(AUX3V4)
N20444590: J15.1(LGKPWR) J16.1(LGKPWR) R128.2
N20444593: J15.2(VIN_SNS) J16.2(VIN_SNS) R127.2
N20444599: J15.4(AUXFAULTB) J16.4(AUXFAULTB) R118.2
N20444659: J15.13(WDI/RESETB) J16.13(WDI/RESETB) R117.2
N20444662: J15.14(SHARE_CLK) J16.14(SHARE_CLK) R116.2
N20444665: J15.15(FAULT0) J16.15(FAULT0) R122.2 R123.2
N20444668: J15.16(FAULT1) J16.16(FAULT1) R121.2 R124.2
N20444671: J15.17(FAULT2) J16.17(FAULT2) R120.2 R125.2
N20444674: J15.18(FAULT3) J16.18(FAULT3) R119.2 R126.2
N20459666: JP4.1 R132.2 SW0.1 SW0.2
N20459768: C46.2 R132.1
N20460722: JP5.1 R133.2 SW1.1 SW1.2
N20460740: C47.2 R133.1
N20465390: JP6.1 R134.2 SW2.1 SW2.2
N20465408: C45.2 R134.1
N20465718: JP7.1 R135.2 SW3.1 SW3.2
N20465754: C48.2 R135.1
N20623237: JP9.2 U2.5(\\~{SHDN})
N20623451: R80.1 R85.2 U2.2(ADJ)
N20700720: D9.1(CATHODE) R114.1
N20701661: D8.1(CATHODE) R113.1
N20745285: Q1.1(G) R84.2 R88.1
N20816983: D3.1(CATHODE) Q7.3(D)
N20816985: D2.1(CATHODE) Q6.3(D)
N20816987: D4.1(CATHODE) Q8.3(D)
N20817990: D1.1(CATHODE) Q4.3(D)
N20817993: D5.2(ANODE) R103.2
N20817996: D1.2(ANODE) R102.2
N20818842: D4.2(ANODE) R106.2
N20818860: D2.2(ANODE) R104.2
N20818872: D3.2(ANODE) R105.2
N20818888: D9.2(ANODE) Q12.3(D)
N20818900: D8.2(ANODE) Q11.3(D)
N20818912: D7.2(ANODE) Q10.3(D)
N20818917: D6.1(CATHODE) R111.1
N20818923: D6.2(ANODE) Q9.3(D)
N21099824: D5.1(CATHODE) Q5.3(D)
N21346099: C37.1 U2.4(BYP)
N21346101: D7.1(CATHODE) R112.1

Not connected (* = marked no-connect by the designer): J14 7(GPIO_1)* 8(OUTEN_0)* 9(OUTEN_1)*; SW0 4 5 6; SW1 4 5 6; SW2 4 5 6; SW3 4 5 6

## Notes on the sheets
sheet 2
- OPTIONAL ZERO OHM JUMPERS FOR PARALLEL OPERATION
- OPTIONAL EXTERNAL +3.3V / 500mA LDO (+3.3V BIAS)
- OPTIONAL SYSTEM 3V3 /100mA
- CHANNEL 0 II CHANNEL 3
- CHANNEL 1 II CHANNEL 2
- OPT
- +3.3V BIAS
- OFF
- *Note: Vin range=3.5V to 15V, Iout= 500mA max, Iq=30uA
- OPTIONAL DYNAMIC LOAD STEP CIRCUIT
- DYNAMIC LOAD STEP CIRCUIT FOR CHANNEL 0 or CHANNEL 1
- DYNAMIC LOAD STEP CIRCUIT FOR CHANNEL 2 or CHANNEL 3
- *
- *
- TEST POINTS
- 6.3V
- 1206
- *
- *
- * Note: There is only one resistor R94 or R100 can be stuffed at a time.
- * Note: There is only one resistor R95 or R101 can be stuffed at a time.
- OPTIONAL LEDs INDICATION
- OPTIONAL BLEEDER  LOADs
- PGOOD0
- PGOOD1
- PGOOD2
- PGOOD3
- PWRGD
- 0805
- 0805
- 0805
- 0805
- NOTE: UNLESS OTHERWISE SPECIFIED
- ALERTB
- FAULTB0
- FAULTB1
- AUXFAULTB
- 1.  ALL RESISTORS ARE IN OHMS, 0603.
  2.  ALL CAPACITORS ARE IN MICROFARADS, 0603.
sheet 3
- OPTIONAL EEPROM IDENTIFICATION, DC1613A CONNECTOR and BOARD TO BOARD PMBUS CONNECTORS (DEMO BOARD ONLY)
- HIROSE DF3A-4P-2DSA
- TO DC2086A
- FCI 98414-G06-12ULF
- TO DC1613A
- Mill Max 803-43-020-20-001000
- Mill Max 802-40-020-20-001000
- 6.3V
- 0603
- PCA ADDITIONAL PARTS
- CTRL0
- CTRL1
- CTRL2
- CTRL3
- *Note: CONTROL0 is used to cascade sequence ON of all channels
- NOTE: UNLESS OTHERWISE SPECIFIED
- 1.  ALL RESISTORS ARE IN OHMS, 0603.
  2.  ALL CAPACITORS ARE IN MICROFARADS, 0603.
